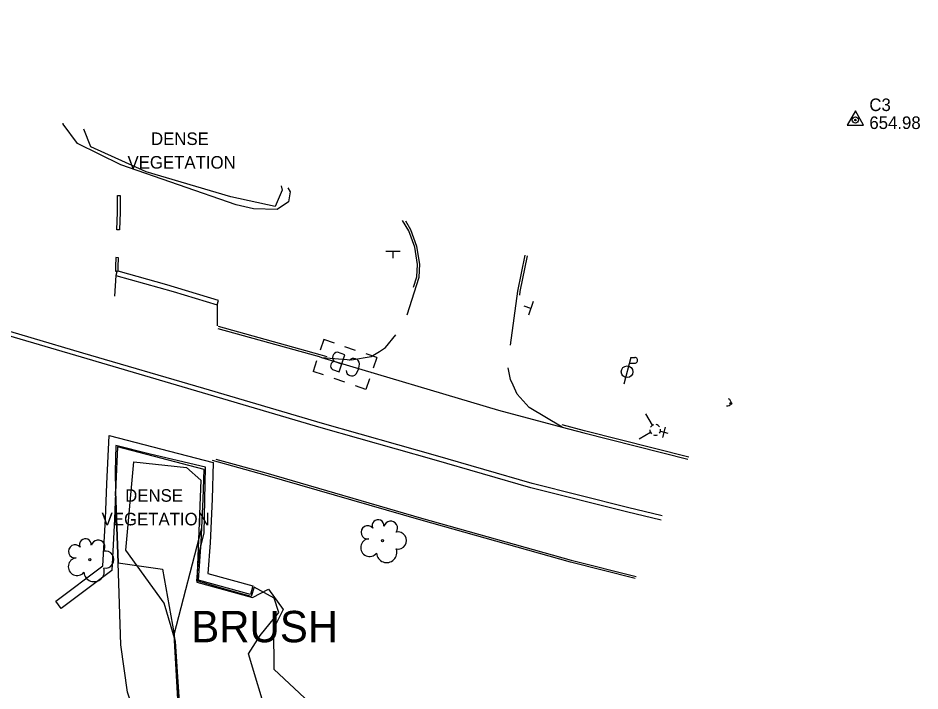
# Model space of a CAD drawing. Extents: x 2129547 to 2134906, y 657330 to 659734.
# Drawn here: x 2132793.8 to 2132995.1, y 658936.3 to 659086.4 of the extents above; entities that cross this region are included whole.
import ezdxf

# ---------------------------------------------------------------- set-up
doc = ezdxf.new("R2010")
doc.units = 0
for name, color, linetype in [('Default', 7, 'Continuous'), ('DR_X_Cells', 7, 'Continuous'), ('DR_X_Culvert', 7, 'Continuous'), ('HY_X_Water_Edge', 7, 'Continuous'), ('PM_X_CL_Double_Solid2', 7, 'Continuous'), ('PV_X_Curb', 7, 'Continuous'), ('PV_X_CURB2', 7, 'Continuous'), ('PV_X_EOP2', 7, 'Continuous'), ('PV_X_Walk', 7, 'Continuous'), ('RD_X_Misc_Items', 7, 'Continuous'), ('RD_X_Wall', 7, 'Continuous'), ('SN_X_Public', 7, 'Continuous'), ('SV_P_Aerial_Targets', 7, 'Continuous'), ('UT_X_Electric_Cells', 7, 'Continuous'), ('UT_X_Misc_Cells', 7, 'Continuous'), ('UT_X_Water_Cells', 7, 'Continuous'), ('VG_X_Cells', 7, 'Continuous'), ('VG_X_Shrub_Line_Lt', 7, 'Continuous'), ('VG_X_Text', 7, 'Continuous'), ('VG_X_Tree_Line_Lt', 7, 'Continuous')]:
    doc.layers.add(name, color=color, linetype=linetype)

# ---------------------------------------------------------------- blocks, each defined once
blk = doc.blocks.new('DM')
at = {"layer": 'UT_X_Misc_Cells'}
blk.add_circle((0, 0), 0.00254, dxfattribs=at)
blk.add_arc((0.01016, 0), 0.01016, 90, 270, dxfattribs=at)
blk = doc.blocks.new('FCTRL')
at = {"layer": 'SV_P_Aerial_Targets'}
blk.add_lwpolyline([(-0.0229, -0.0147), (0.0229, -0.0147), (0, 0.0262)], close=True, dxfattribs=at)
for radius in [0.00889, 0.00203]:
    blk.add_circle((0, 0), radius, dxfattribs=at)
blk = doc.blocks.new('FH')
at = {"layer": 'UT_X_Water_Cells'}
for p, q in [((0.0152, 0.0262), (-0.0153, 0.0262)), ((0, 0.0153), (0, 0.0371)), ((-0.0108, -0.0108), (-0.0372, -0.0372)), ((0.0107, -0.0108), (0.0371, -0.0372))]:
    blk.add_line(p, q, dxfattribs=at)
for start, end in [(140.021, 184.0629), (68.1395, 112.038), (356.0165, 39.9889), (211.8788, 255.8479), (283.8239, 329.9097)]:
    blk.add_arc((0, 0), 0.0152, start, end, dxfattribs=at)
blk = doc.blocks.new('PP')
at = {"layer": 'UT_X_Electric_Cells'}
for p, q in [((0.0109, 0.0406), (-0.0095, -0.0356)), ((0.0109, 0.0406), (0.0217, 0.0406)), ((0.0065, 0.0244), (0.0217, 0.0244))]:
    blk.add_line(p, q, dxfattribs=at)
blk.add_circle((0, 0), 0.0165, dxfattribs=at)
blk.add_arc((0.0218, 0.0325), 0.0081, 268.8767, 91.1233, dxfattribs=at)
blk = doc.blocks.new('SGN1P')
at = {"layer": 'SN_X_Public'}
for p, q in [((0, 0), (-0.02032, 0)), ((0, 0.02032), (0, -0.02032))]:
    blk.add_line(p, q, dxfattribs=at)
blk = doc.blocks.new('TREE')
at = {"layer": 'VG_X_Cells'}
blk.add_circle((0, 0), 0.00305, dxfattribs=at)
for centre, radius, start, end in [((-0.0125, 0.0428), 0.0167, 354.0047, 205.9741), ((0.0232, 0.0359), 0.0197, 323.83, 165.0376), ((-0.042, 0.0237), 0.0187, 39.0625, 279.5412), ((-0.0362, -0.0197), 0.0251, 96.1722, 320.5737), ((0.0439, 0.0005), 0.0243, 259.1453, 101.4596), ((0.012, -0.0331), 0.029, 184.9476, 19.4572)]:
    blk.add_arc(centre, radius, start, end, dxfattribs=at)
blk = doc.blocks.new('POINT_DISPLAY')
at = {"layer": 'Default'}
blk.add_line((0, 0), (0, 0), dxfattribs=at)
blk = doc.blocks.new('GCB-X')
at = {"layer": 'Default'}
for p, q in [((-0.0317, 0.019), (-0.019, 0.019)), ((-0.0317, 0.0063), (-0.0317, 0.019)), ((-0.0063, 0.019), (0.0063, 0.019)), ((0.019, 0.019), (0.0317, 0.019)), ((0.0317, 0.0063), (0.0317, 0.019)), ((0.0034, 0.0007), (0.0124, 0.0007)), ((-0.0317, -0.019), (-0.0317, -0.0063)), ((0.0317, -0.019), (0.0317, -0.0063)), ((-0.0317, -0.019), (-0.019, -0.019)), ((-0.0063, -0.019), (0.0063, -0.019)), ((0.019, -0.019), (0.0317, -0.019))]:
    blk.add_line(p, q, dxfattribs=at)
blk.add_lwpolyline([(0.0116, 0.0099), (0.0034, 0.0099), (0.0034, -0.0104), (0.0124, -0.0104)], dxfattribs=at)
for centre, radius, start, end in [((0.0071, 0), 0.0233, 164.8107, 195.1893), ((-0.0094, 0.0037), 0.00645, 21.5603, 158.4397), ((0.0101, 0.0051), 0.00501, 296.8207, 73.0013), ((0.0101, -0.0049), 0.00597, 292.0547, 67.9453), ((-0.0094, -0.0037), 0.00645, 201.5603, 338.4397)]:
    blk.add_arc(centre, radius, start, end, dxfattribs=at)
for p in [(0, 0.019), (0, 0.019), (-0.0317, 0), (0, 0), (0, 0), (0, 0), (0.0317, 0), (0, -0.019), (0, -0.019)]:
    blk.add_blockref('POINT_DISPLAY', p, dxfattribs=at)

msp = doc.modelspace()

# ---------------------------------------------------------------- linework, layer by layer
at = {"layer": 'DR_X_Culvert'}
msp.add_lwpolyline([(2132845.71, 658957.83), (2132834.09, 658960.98), (2132834.7, 658969.49), (2132835.15, 658979.12), (2132835.36, 658985.74), (2132816.05, 658990.74), (2132815.64, 658982.41), (2132815.36, 658974.62), (2132814.75, 658963.15), (2132803.48, 658954.71), (2132802.28, 658956.31), (2132812.8, 658964.19), (2132813.36, 658974.71), (2132813.65, 658982.5), (2132814.17, 658993.29), (2132837.41, 658987.27), (2132837.15, 658979.05), (2132836.7, 658969.37), (2132836.2, 658962.48), (2132846.24, 658959.77)], close=True, dxfattribs=at)
at = {"layer": 'HY_X_Water_Edge'}
for points in [[(2132839.86, 658867), (2132836.34, 658867.58), (2132836.22, 658870.49), (2132835.5, 658879.69), (2132834.12, 658884.97), (2132832.8, 658890.55), (2132829.28, 658901.08), (2132826.09, 658909.43), (2132825.08, 658914.78), (2132821.02, 658927.88), (2132819.9, 658931.19), (2132818.26, 658936.03), (2132816.8, 658946.57), (2132816.15, 658964.85), (2132815.59, 658980.83)], [(2132839.86, 658867), (2132844.49, 658866.25), (2132843.65, 658877.53), (2132841.8, 658887.6), (2132841, 658890.66), (2132840.38, 658893.05), (2132834.49, 658911.74), (2132831.84, 658922.87), (2132829.47, 658934.44), (2132828.65, 658948.92), (2132834.85, 658972.67)]]:
    msp.add_lwpolyline(points, dxfattribs=at)
at = {"layer": 'PM_X_CL_Double_Solid2'}
for points in [[(2132937.34, 658974.37), (2132929.56, 658976.28), (2132908.25, 658981.62), (2132886.67, 658987.86), (2132861.48, 658994.98), (2132835, 659002.78), (2132808.02, 659010.73), (2132784.91, 659017.54), (2132763.23, 659024.09), (2132739.46, 659030.83), (2132716.26, 659037.56), (2132694.6, 659043.83), (2132670.64, 659050.64), (2132645.84, 659057.85), (2132619.01, 659065.45), (2132594.35, 659072.98), (2132570.83, 659079.68), (2132549.69, 659085.46)], [(2132937.57, 658975.34), (2132929.8, 658977.25), (2132908.51, 658982.59), (2132886.94, 658988.82), (2132861.75, 658995.94), (2132835.28, 659003.74), (2132808.3, 659011.69), (2132785.19, 659018.49), (2132763.51, 659025.05), (2132739.74, 659031.79), (2132716.54, 659038.52), (2132694.88, 659044.79), (2132670.92, 659051.6), (2132646.12, 659058.82), (2132619.29, 659066.41), (2132594.63, 659073.94), (2132571.1, 659080.64), (2132549.95, 659086.43)]]:
    msp.add_lwpolyline(points, dxfattribs=at)
at = {"layer": 'PV_X_Curb'}
msp.add_lwpolyline([(2132943.47, 658988.44), (2132920.19, 658994.35), (2132915.26, 658995.67)], dxfattribs=at)
at = {"layer": 'PV_X_CURB2'}
for points in [[(2132882.09, 659026.37), (2132882.83, 659028.7), (2132882.97, 659031.46), (2132882.35, 659035.3), (2132881.01, 659038.98), (2132879.63, 659041.29)], [(2132905.76, 659024.58), (2132905.87, 659025.39), (2132907.49, 659033.4)], [(2132838.51, 659017.69), (2132861.15, 659011.37), (2132862.7, 659010.9)], [(2132931.51, 658961.4), (2132917.12, 658965.02), (2132883.75, 658974.38), (2132848.98, 658984.47), (2132837.21, 658987.73)]]:
    msp.add_lwpolyline(points, dxfattribs=at)
at = {"layer": 'PV_X_EOP2'}
for points in [[(2132880.65, 659020.2), (2132883.32, 659028.61), (2132883.48, 659031.48), (2132882.83, 659035.43), (2132881.47, 659039.19), (2132880.33, 659041.1)], [(2132903.74, 659013.45), (2132905.38, 659025.48), (2132907.01, 659033.54)], [(2132838.43, 659017.19), (2132861.01, 659010.89), (2132861.56, 659010.72), (2132901.03, 658998.93), (2132915.23, 658995.16), (2132920.07, 658993.87), (2132943.26, 658987.98)], [(2132861.56, 659010.72), (2132868.2, 659010.14), (2132872.63, 659010.91), (2132874.52, 659012.04), (2132875.84, 659012.9), (2132878.09, 659015.73)], [(2132915.23, 658995.16), (2132907.9, 658999.51), (2132905.18, 659002.53), (2132904.29, 659004.49), (2132903.7, 659005.75), (2132903.15, 659008.42)], [(2132837.96, 658988.04), (2132849.11, 658984.95), (2132883.89, 658974.86), (2132917.25, 658965.51), (2132931.71, 658961.86)]]:
    msp.add_lwpolyline(points, dxfattribs=at)
at = {"layer": 'PV_X_Walk'}
for p, q in [((2132815.68, 659029.02), (2132815.4, 659024.35)), ((2132838.25, 659022.46), (2132838.28, 659017.75))]:
    msp.add_line(p, q, dxfattribs=at)
at = {"layer": 'RD_X_Misc_Items'}
for points in [[(2132851.2, 659044.35), (2132841.33, 659046.54), (2132822.45, 659052.12), (2132810.05, 659057.69), (2132808.55, 659061.61)], [(2132852.53, 659049), (2132852.78, 659048.05), (2132851.2, 659044.35)], [(2132849.67, 658930.01), (2132845.25, 658944.59), (2132847.87, 658948.7), (2132852.03, 658953.79), (2132850.96, 658957.03), (2132846.53, 658959.47), (2132845.89, 658957.37), (2132839.99, 658959.01), (2132833.7, 658960.83), (2132834.29, 658967.04), (2132835.37, 658971.6), (2132835.7, 658986.24), (2132823.31, 658989.14), (2132815.7, 658991.05), (2132815.49, 658985.29), (2132815.59, 658980.83), (2132816.15, 658964.85), (2132826.08, 658963.5), (2132828.65, 658948.92), (2132829.47, 658934.44)]]:
    msp.add_lwpolyline(points, dxfattribs=at)
at = {"layer": 'RD_X_Wall'}
msp.add_lwpolyline([(2132816.63, 659046.87), (2132816.61, 659043.12), (2132816.45, 659039.15), (2132815.85, 659039.17), (2132816.01, 659043.13), (2132816.03, 659046.87)], close=True, dxfattribs=at)
for points in [[(2132816.21, 659029.95), (2132816.2, 659030.95), (2132816.28, 659032.96), (2132815.68, 659032.99), (2132815.6, 659030.96), (2132815.61, 659029.94), (2132815.86, 659029.84)], [(2132815.86, 659029.84), (2132815.68, 659029.02), (2132828.48, 659025.41), (2132838.25, 659022.46), (2132838.54, 659023.42), (2132827.04, 659026.87), (2132816.21, 659029.95)], [(2132815.86, 659029.84), (2132815.91, 659030.04), (2132816.21, 659029.95)]]:
    msp.add_lwpolyline(points, dxfattribs=at)
at = {"layer": 'VG_X_Shrub_Line_Lt'}
msp.add_lwpolyline([(2132830.28, 658931.55), (2132829.79, 658934.95), (2132829.01, 658947.32), (2132826.44, 658955.9), (2132817.88, 658967.72), (2132819.67, 658987.42), (2132831.4, 658986.17), (2132834.64, 658983.32), (2132833.71, 658960.55), (2132846.18, 658957.11), (2132849.7, 658959.04), (2132853, 658954.46), (2132850.83, 658950.16), (2132850.88, 658941.13), (2132858.92, 658933.66), (2132871.87, 658928.41), (2132874.34, 658921.11), (2132877.03, 658917.44), (2132897.21, 658916.11), (2132903.49, 658916.29)], dxfattribs=at)
at = {"layer": 'VG_X_Tree_Line_Lt'}
msp.add_lwpolyline([(2132854.01, 659048.58), (2132854.52, 659047.67), (2132854.19, 659045.42), (2132851.67, 659043.73), (2132846.36, 659043.89), (2132842.5, 659044.76), (2132816.75, 659053.68), (2132807.08, 659058.44), (2132803.93, 659062.72), (2132803.88, 659062.95)], dxfattribs=at)

# ---------------------------------------------------------------- block references
at = {"layer": 'DR_X_Cells', "xscale": 196.85000000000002, "yscale": 196.85, "rotation": 161.28141102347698}
msp.add_blockref('GCB-X', (2132866.76, 659009.13), dxfattribs=at)
at = {"layer": 'SN_X_Public', "yscale": 78.74000000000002}
for p, xscale, rotation in [((2132877.46, 659034.43), 78.74000000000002, 90.24932731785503), ((2132908.25, 659021.65), 78.74000000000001, -17.93440179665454)]:
    msp.add_blockref('SGN1P', p, dxfattribs=dict(at, xscale=xscale, rotation=rotation))
at = {"layer": 'SV_P_Aerial_Targets', "xscale": 78.74000000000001, "yscale": 78.74000000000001}
msp.add_blockref('FCTRL', (2132980.64, 659063.67), dxfattribs=at)
at = {"layer": 'UT_X_Electric_Cells', "xscale": 78.74000000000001, "yscale": 78.74000000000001}
msp.add_blockref('PP', (2132929.72, 659007.51), dxfattribs=at)
at = {"layer": 'UT_X_Misc_Cells', "xscale": 78.74000000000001, "yscale": 78.74, "rotation": 162.93716705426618}
msp.add_blockref('DM', (2132952.87, 659000.44), dxfattribs=at)
at = {"layer": 'UT_X_Water_Cells', "xscale": 78.74000000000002, "yscale": 78.74000000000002, "rotation": -105.05112393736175}
msp.add_blockref('FH', (2132935.99, 658994.54), dxfattribs=at)
at = {"layer": 'VG_X_Cells', "xscale": 78.74000000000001, "yscale": 78.74000000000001}
for p in [(2132875.14, 658969.82), (2132809.87, 658965.57)]:
    msp.add_blockref('TREE', p, dxfattribs=at)

# ---------------------------------------------------------------- texts
at = {"layer": 'SV_P_Aerial_Targets'}
for s, p in [('C3', (2132983.76, 659065.67)), ('654.98', (2132983.76, 659061.67))]:
    msp.add_text(s, height=2.8, dxfattribs=at).set_placement(p)
at = {"layer": 'VG_X_Text'}
for s, height, p in [('DENSE', 2.8, (2132823.51, 659058.1)), ('VEGETATION', 2.8, (2132818.27, 659052.83)), ('DENSE', 2.8, (2132817.74, 658978.51)), ('VEGETATION', 2.8, (2132812.49, 658973.24)), ('BRUSH', 7, (2132832.49, 658947.16))]:
    msp.add_text(s, height=height, dxfattribs=at).set_placement(p)

doc.saveas('drawing.dxf')
